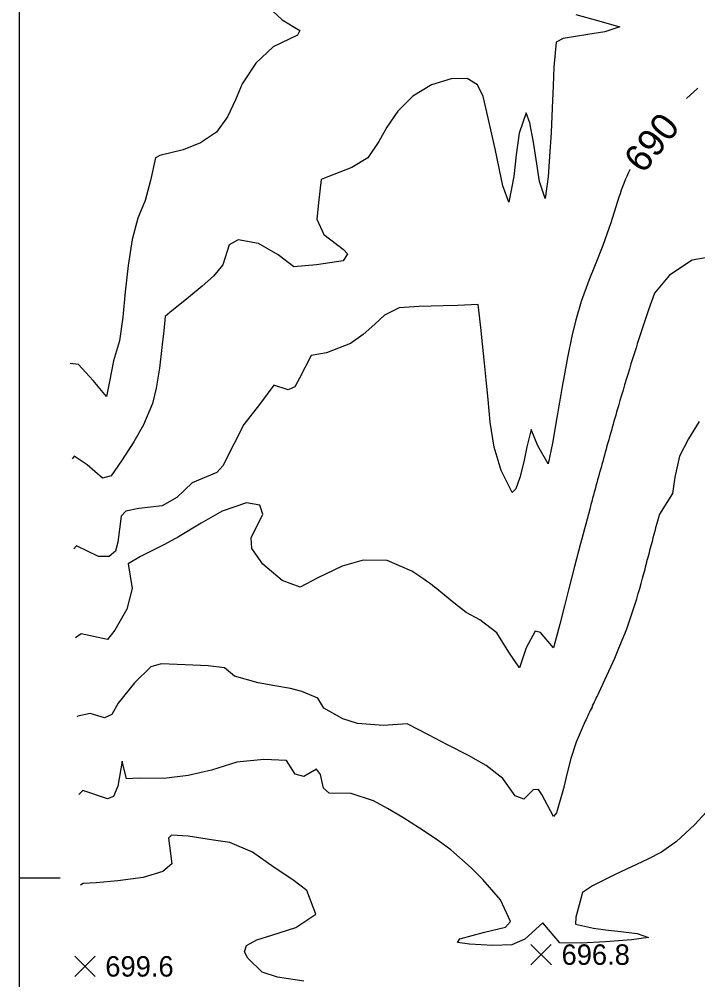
# Model space of a CAD drawing. Extents: x 2566079 to 2571326, y 424054 to 426896.
# Drawn here: x 2566079 to 2566578, y 424925 to 425631 of the extents above; entities that cross this region are included whole.
import ezdxf

# ---------------------------------------------------------------- set-up
doc = ezdxf.new("R2010")
doc.units = 0
for name, color, linetype in [('Contour_ADS_Label_Major', 7, 'Continuous'), ('Contour_ADS_Major', 7, 'Continuous'), ('Contour_ADS_Minor', 7, 'Continuous'), ('Contour_ADS_Spot_Elevation', 7, 'Continuous'), ('Contour_ADS_State_Plane_Border', 7, 'Continuous')]:
    doc.layers.add(name, color=color, linetype=linetype)

# ---------------------------------------------------------------- blocks, each defined once
blk = doc.blocks.new('S750')
at = {"layer": 'Contour_ADS_Spot_Elevation'}
for p, q in [((-0.5, 0.498), (0.5, -0.498)), ((-0.498, -0.5), (0.498, 0.5))]:
    blk.add_line(p, q, dxfattribs=at)

msp = doc.modelspace()

# ---------------------------------------------------------------- linework, layer by layer
at = {"layer": 'Contour_ADS_Major'}
for p, q in [((2566577.93, 425580.06), (2566569.68, 425572.35)), ((2566528.03, 425520.3), (2566527.89, 425520.05))]:
    msp.add_line(p, q, dxfattribs=at)
for points in [[(2566519.93, 425499.89), (2566513.99, 425481.15), (2566508.17, 425464.44), (2566502.6, 425450.19), (2566497.93, 425438.77), (2566492.22, 425423.41), (2566488.02, 425408.92), (2566485.42, 425397.96), (2566482.21, 425382.12)], [(2566474.46, 425338.05), (2566471.28, 425319.2), (2566468.08, 425304.15), (2566460.44, 425317.32), (2566455.51, 425329.35), (2566452.3, 425316.67), (2566450, 425305.58), (2566447.14, 425294.07), (2566444.19, 425285.67), (2566441.48, 425283.02), (2566433.41, 425299.2), (2566428.33, 425316.42), (2566425.47, 425334.61), (2566423.99, 425351.23), (2566422.74, 425363.37), (2566421.23, 425377.94), (2566419.76, 425392.3), (2566418.6, 425404.18), (2566416.51, 425421.1), (2566401.28, 425420.32), (2566390.85, 425420.04), (2566373.18, 425419.77), (2566358.45, 425418.76), (2566347.85, 425413.18), (2566340.55, 425406.72), (2566332.05, 425399.13), (2566322.84, 425392.39), (2566305.1, 425385.63), (2566293.95, 425383.68), (2566285.36, 425366.92), (2566281.89, 425360.66), (2566276.9, 425358.53), (2566266.31, 425361.76), (2566255.95, 425347.62), (2566244.44, 425333.07), (2566237.37, 425319.04), (2566229.03, 425302.69), (2566224.46, 425297.65), (2566206.32, 425290.22), (2566195.18, 425279.29), (2566184.44, 425273.29), (2566167.28, 425271.34), (2566157.67, 425269.41), (2566154.2, 425265.52), (2566151.69, 425246.6), (2566150.08, 425239.94), (2566145.33, 425236.07), (2566137.59, 425235.96), (2566121.42, 425243.76), (2566119.51, 425241.64)]]:
    msp.add_lwpolyline(points, dxfattribs=at)
for centre, radius, start, end in [((2566694.99, 425442.42), 184.25, 155.08193, 161.82576), ((2568153.47, 425069.45), 1700.26, 169.40325, 170.13365), ((2571865.03, 424425.25), 5467.31, 170.14733, 170.38912)]:
    msp.add_arc(centre, radius, start, end, dxfattribs=at)
at = {"layer": 'Contour_ADS_Minor'}
for points in [[(2566258.5, 425643.29), (2566272.61, 425630.24), (2566285.43, 425622.44), (2566283.91, 425618.97), (2566265.98, 425610.37), (2566253.23, 425598.29), (2566243.04, 425583.13), (2566238.18, 425571.45), (2566232.43, 425558.86), (2566224.18, 425547.7), (2566212.58, 425539.78), (2566199.89, 425534.82), (2566182.63, 425530.48), (2566179.47, 425528.82), (2566175.81, 425512.27), (2566171.76, 425497.62), (2566166.42, 425484.56), (2566162.37, 425468.94), (2566159.41, 425449.82), (2566157.18, 425430.43), (2566155.38, 425411.86), (2566153.12, 425394.44), (2566148.58, 425379.82), (2566145.69, 425364.48), (2566143.44, 425353.54), (2566133.79, 425365.34), (2566122.96, 425377.08), (2566116.85, 425377.75)], [(2566488.26, 425634.15), (2566504.32, 425629.84), (2566520.53, 425625.08), (2566509.55, 425621.53), (2566497.21, 425619.48), (2566479.11, 425616.4), (2566473.88, 425613.79), (2566472.08, 425595.39), (2566471.62, 425581.69), (2566471.01, 425565.28), (2566470.14, 425547.37), (2566469.09, 425529.89), (2566467.97, 425515), (2566465.8, 425498.87), (2566461.63, 425511.39), (2566459.64, 425524.42), (2566457.23, 425540.31), (2566454.54, 425554.55), (2566451.79, 425561.85), (2566446.71, 425546.9), (2566444.54, 425531.18), (2566442.66, 425515.24), (2566439.12, 425496.32), (2566434.72, 425508.28), (2566432, 425521.35), (2566428.93, 425535.42), (2566425.77, 425549.37), (2566422.86, 425562.44), (2566420.14, 425573.8), (2566416.04, 425582.39), (2566408.58, 425587.06), (2566396.63, 425586.97), (2566382.29, 425582.48), (2566368.48, 425574.25), (2566357.54, 425563.21), (2566349.46, 425551.35), (2566343.68, 425540.93), (2566335.55, 425528.79), (2566323.64, 425521.64), (2566306.19, 425514.83), (2566301.08, 425512.88), (2566299.22, 425495.88), (2566298.12, 425483.71), (2566303.26, 425472.55), (2566317.66, 425461.41), (2566320.53, 425458.25), (2566317.35, 425453.13), (2566297.81, 425450.23), (2566281.11, 425448.84), (2566269.63, 425457.71), (2566255.15, 425465.81), (2566240.27, 425468.55), (2566233.58, 425464.88), (2566228.88, 425450.18), (2566222.1, 425441.97), (2566213.64, 425434.51), (2566203.67, 425426.29), (2566189.92, 425415.35), (2566186.58, 425412.23), (2566185.51, 425401.79), (2566184.24, 425389.53), (2566182.37, 425374.35), (2566180, 425359.72), (2566177.18, 425348.32), (2566170.65, 425332.69), (2566163.62, 425320.31), (2566154.46, 425306.33), (2566146.81, 425295.17), (2566140.61, 425293.52), (2566129.34, 425303.27), (2566119.82, 425309.78), (2566118.22, 425307.72)], [(2566584.84, 425455.66), (2566573.88, 425453.74), (2566557.22, 425442.76), (2566546.07, 425429.54), (2566541.71, 425417.19), (2566536.35, 425401.06)], [(2566578.9, 425335.29), (2566571.09, 425322.54), (2566564.46, 425309.81), (2566560.95, 425294.39), (2566559.34, 425282.38), (2566549.71, 425267.02)], [(2566367.89, 425225.17), (2566349.66, 425232.95), (2566332.02, 425233.32), (2566316.67, 425228.82), (2566298.82, 425220.24), (2566285.77, 425213.36), (2566272.48, 425218.47), (2566258.43, 425230.37), (2566250.14, 425241.94), (2566249.82, 425249.76), (2566258.3, 425266.98), (2566256.25, 425273.72), (2566246.41, 425275.41), (2566228.37, 425269.24), (2566212.93, 425260.51), (2566196.29, 425250.48), (2566186.14, 425244.82), (2566168.47, 425235.9), (2566159.49, 425230.73), (2566162.42, 425212.49), (2566158.34, 425197.21), (2566149.48, 425181.96), (2566144.29, 425175.09), (2566124.91, 425179.3), (2566120.79, 425176.23)], [(2566491.74, 425245.45), (2566487.33, 425228.68), (2566483.01, 425211.6), (2566480, 425199.83), (2566476.5, 425186.38), (2566471.79, 425169), (2566462.35, 425180.15), (2566458.44, 425181.22), (2566451.86, 425168.84), (2566446.95, 425154.29), (2566439.11, 425165.69), (2566430.2, 425180.01), (2566417.81, 425189.5), (2566407.82, 425194.94), (2566398.59, 425201.99), (2566384.84, 425213.27)], [(2566495.24, 425114.98), (2566488.65, 425099.54), (2566484.68, 425087.72), (2566481.95, 425077), (2566479.31, 425065.67), (2566474.16, 425047.74), (2566471.92, 425045.04), (2566463.22, 425061.15), (2566461, 425064.87), (2566456.89, 425064.69), (2566450.08, 425057.72), (2566443.8, 425060.22), (2566434.56, 425072.95), (2566422.39, 425082.5), (2566409.35, 425089.74), (2566394.02, 425097.73), (2566380.17, 425104.92), (2566364.32, 425112.97), (2566346.97, 425111.95), (2566327.86, 425113.42), (2566317.15, 425116.66), (2566303.09, 425124.52), (2566298.79, 425131.93), (2566286.91, 425136.89), (2566278.59, 425138.93), (2566267.26, 425141), (2566254.99, 425143.15), (2566237.53, 425148.14), (2566230.16, 425154.27), (2566218.12, 425155.71), (2566201.15, 425156.51), (2566183.68, 425157.17), (2566175.95, 425154.92), (2566164.01, 425143.17), (2566152.14, 425128.17), (2566147.48, 425119.95), (2566142.09, 425117.48), (2566131.59, 425120.68), (2566122.34, 425118.63), (2566121.93, 425118.24)], [(2566584.3, 425048.46), (2566575.46, 425038.76), (2566562.22, 425026.53), (2566551.3, 425018.87), (2566541.26, 425013.75), (2566529.12, 425007.95), (2566517.27, 425002.36), (2566500.59, 424994.07), (2566493.26, 424989.25), (2566488.3, 424971.02), (2566488.07, 424965.99), (2566501.26, 424962.85), (2566510.22, 424961.73), (2566521.32, 424960.47), (2566533.41, 424959.11), (2566541.62, 424956.06), (2566529.18, 424954.4), (2566510.15, 424952.94), (2566492.25, 424952), (2566476.53, 424952.13), (2566463.99, 424966.98), (2566450.87, 424954.89), (2566441.18, 424950.78), (2566427.4, 424950.36), (2566410.17, 424951.16), (2566401.42, 424952.44), (2566403.08, 424955.23), (2566421.25, 424960.15), (2566436.71, 424963.82), (2566440.41, 424967.76), (2566433.06, 424983.87), (2566420.06, 424998.78), (2566411.45, 425007.33), (2566396.57, 425020.41), (2566385.71, 425028.32), (2566373.54, 425036.43), (2566361.25, 425044.17), (2566349.85, 425050.96), (2566339.64, 425056.4), (2566323.3, 425062), (2566307.13, 425062.21), (2566302.86, 425065.76), (2566300.6, 425075.9), (2566297.82, 425079.7), (2566288.36, 425074.43), (2566282.14, 425076.16), (2566275.61, 425086.25), (2566259.17, 425086.84), (2566239.32, 425084.97), (2566220.7, 425079.06), (2566203.4, 425075.11), (2566185.66, 425072.99), (2566167.48, 425073.26), (2566158.17, 425072.58), (2566155.05, 425085.74), (2566151.79, 425067.26), (2566148.64, 425059.64), (2566144.18, 425058), (2566126.02, 425064.19), (2566123.04, 425061.16)], [(2566288.36, 424923.92), (2566269.23, 424926.96), (2566257.84, 424930.65), (2566247.38, 424940.84), (2566244.75, 424945.66), (2566246.37, 424950.35), (2566254.02, 424954.42), (2566265.01, 424957.89), (2566282.64, 424963.52), (2566297.22, 424973.3), (2566290.72, 424990.76), (2566280.35, 424998.38), (2566266.55, 425007.47), (2566250.68, 425018.88), (2566234.01, 425025.81), (2566222.12, 425027.57), (2566203.43, 425030.49), (2566191.32, 425031.21), (2566188.95, 425028.98), (2566191.49, 425010.3), (2566184.86, 425004.62), (2566170.43, 425000.21), (2566151.85, 424997.83), (2566135.82, 424996.3), (2566126.23, 424995.72), (2566124.34, 424994.63)]]:
    msp.add_lwpolyline(points, dxfattribs=at)
for centre, radius, start, end in [((2568128.09, 424881.96), 1674.24, 161.93779, 162.78599), ((2568436.69, 424787.65), 1996.93, 162.82163, 163.74226), ((2569558.64, 424466.18), 3164.02, 163.84155, 164.52589), ((2571478.18, 423933.43), 5156.12, 164.51149, 164.92723), ((2572070.28, 423767.98), 5770.87, 164.869792, 165.165897), ((2567425.94, 425019.12), 910.62, 164.20315, 165.501), ((2568243.13, 424804.84), 1755.44, 165.40764, 165.86417), ((2565888.69, 425393.35), 671.45, 345.03911, 346.23269), ((2566275.33, 425075.31), 176.13, 51.55823, 58.29908), ((2566027.55, 425358.34), 528.27, 341.43373, 344.81966), ((2566101.1, 425341.86), 453.36, 336.54829, 340.44884), ((2565463.52, 425631.25), 1153.51, 334.56746, 335.96477), ((2564892.08, 425901.31), 1785.54, 334.24447, 334.6162), ((2566919.64, 424918.34), 467.74, 153.72079, 155.13988)]:
    msp.add_arc(centre, radius, start, end, dxfattribs=at)
at = {"layer": 'Contour_ADS_State_Plane_Border'}
msp.add_line((2566079.33, 425000), (2566109.33, 425000), dxfattribs=at)
msp.add_lwpolyline([(2566079.33, 424077.11), (2571302.93, 424077.11), (2571302.93, 426873.74), (2566079.33, 426873.74), (2566079.33, 424077.11)], close=True, dxfattribs=at)

# ---------------------------------------------------------------- block references
at = {"layer": 'Contour_ADS_Spot_Elevation', "xscale": 15, "yscale": 15}
for p in [(2566462.84, 424943.55), (2566127.59, 424934.9)]:
    msp.add_blockref('S750', p, dxfattribs=at)

# ---------------------------------------------------------------- texts
at = {"layer": 'Contour_ADS_Label_Major'}
msp.add_text('690', height=20, rotation=51.33498, dxfattribs=at).set_placement((2566537.8, 425516.5))
at = {"layer": 'Contour_ADS_Spot_Elevation'}
for s, p in [('696.8', (2566477.84, 424936.05)), ('699.6', (2566142.59, 424927.4))]:
    msp.add_text(s, height=15, dxfattribs=at).set_placement(p)

doc.saveas('drawing.dxf')
